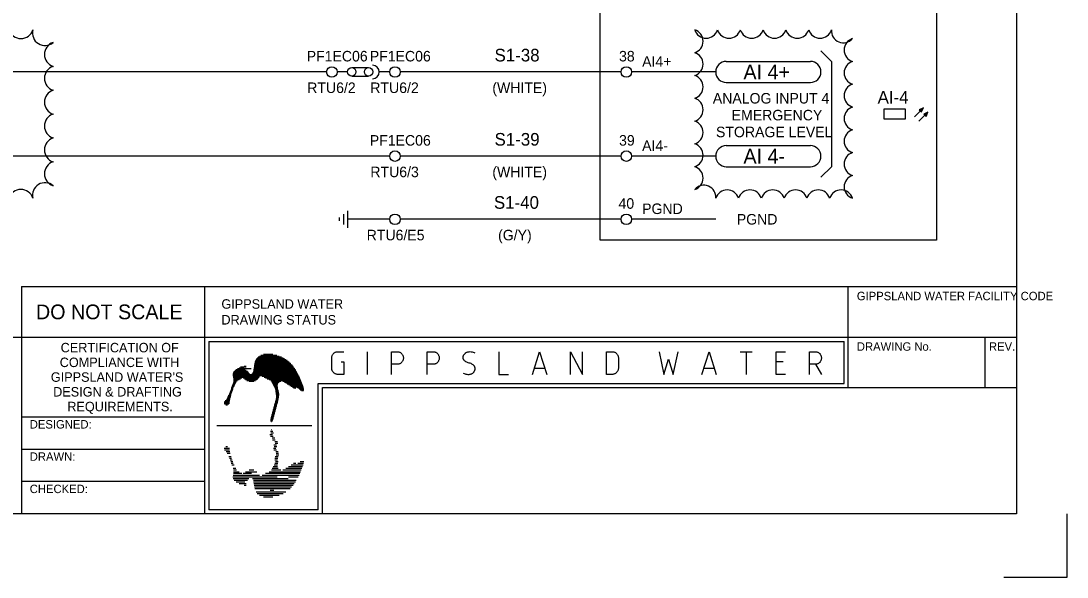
# Model space of a CAD drawing. Extents: x 0 to 841, y 0 to 594.
# Drawn here: x 592.3 to 841, y 0 to 132.1 of the extents above; entities that cross this region are included whole.
import ezdxf

# ---------------------------------------------------------------- set-up
doc = ezdxf.new("R2010")
doc.units = 0
for name, color, linetype in [('A1BORDER', 7, 'Continuous'), ('Level 1', 7, 'Continuous'), ('Level 10', 7, 'Continuous')]:
    doc.layers.add(name, color=color, linetype=linetype)

msp = doc.modelspace()

# ---------------------------------------------------------------- linework, layer by layer
at = {"layer": 'A1BORDER'}
for p, q in [((829, 581), (829, 15)), ((592.5, 69), (592.5, 15)), ((592.5, 69), (829, 69)), ((636, 69), (636, 15)), ((789, 45), (789, 69)), ((28, 57), (829, 57)), ((637, 56), (788, 56)), ((637, 56), (637, 16)), ((788, 46), (788, 56)), ((821.5, 45), (821.5, 57)), ((648.74, 52.32), (654.24, 52.32)), ((649.02, 52.52), (653.76, 52.52)), ((649.39, 52.72), (653.15, 52.72)), ((650.01, 52.92), (652.2, 52.92)), ((644.54, 49.92), (645.36, 49.92)), ((645.37, 50.12), (645.86, 50.12)), ((647.75, 49.92), (657.17, 49.92)), ((647.78, 50.12), (657.02, 50.12)), ((647.81, 50.32), (656.86, 50.32)), ((647.85, 50.52), (656.69, 50.52)), ((647.88, 50.72), (656.5, 50.72)), ((647.91, 50.92), (656.3, 50.92)), ((647.96, 51.12), (656.08, 51.12)), ((648.03, 51.32), (655.85, 51.32)), ((648.12, 51.52), (655.59, 51.52)), ((648.23, 51.72), (655.31, 51.72)), ((648.37, 51.92), (655, 51.92)), ((648.53, 52.12), (654.64, 52.12)), ((642.73, 48.12), (658.25, 48.12)), ((642.74, 47.92), (658.35, 47.92)), ((642.75, 48.32), (646.79, 48.32)), ((642.79, 47.72), (649.08, 47.72)), ((642.81, 48.52), (646.55, 48.52)), ((642.83, 47.52), (648.95, 47.52)), ((642.85, 47.31), (644.88, 47.31)), ((642.9, 48.72), (646.37, 48.72)), ((643.04, 48.92), (646.16, 48.92)), ((643.26, 49.12), (645.9, 49.12)), ((643.54, 49.32), (645.57, 49.32)), ((643.85, 49.52), (647.09, 49.52)), ((644.18, 49.72), (645.89, 49.72)), ((645.14, 47.31), (648.83, 47.31)), ((647.19, 48.32), (658.14, 48.32)), ((647.42, 48.52), (658.03, 48.52)), ((647.54, 48.72), (657.92, 48.72)), ((647.61, 48.92), (657.8, 48.92)), ((647.63, 49.12), (657.68, 49.12)), ((647.66, 49.32), (657.57, 49.32)), ((647.69, 49.52), (657.44, 49.52)), ((647.71, 49.72), (657.31, 49.72)), ((649.72, 47.72), (658.45, 47.72)), ((650.12, 47.52), (658.55, 47.52)), ((650.48, 47.31), (658.64, 47.31)), ((642.35, 44.92), (642.83, 44.92)), ((642.43, 45.12), (642.9, 45.12)), ((642.5, 45.32), (643, 45.32)), ((642.57, 45.52), (643.1, 45.52)), ((642.65, 45.72), (643.2, 45.72)), ((642.72, 45.92), (643.3, 45.92)), ((642.79, 46.12), (643.4, 46.12)), ((642.84, 46.32), (643.5, 46.32)), ((642.87, 47.12), (644.57, 47.12)), ((642.87, 46.52), (643.6, 46.52)), ((642.88, 46.92), (644.23, 46.92)), ((642.88, 46.72), (643.83, 46.72)), ((645.49, 47.12), (648.67, 47.12)), ((645.76, 46.92), (648.42, 46.92)), ((646.05, 46.72), (648.11, 46.72)), ((646.62, 46.52), (647.67, 46.52)), ((650.87, 47.12), (658.73, 47.12)), ((651.36, 46.92), (658.82, 46.92)), ((651.76, 46.72), (658.9, 46.72)), ((651.88, 46.52), (654.15, 46.52)), ((651.99, 46.32), (653.71, 46.32)), ((652.1, 46.12), (653.52, 46.12)), ((652.2, 45.92), (653.4, 45.92)), ((652.31, 45.72), (653.33, 45.72)), ((652.41, 45.52), (653.31, 45.52)), ((652.5, 45.32), (653.34, 45.32)), ((652.6, 45.12), (653.38, 45.12)), ((652.69, 44.92), (653.41, 44.92)), ((654.57, 46.52), (658.99, 46.52)), ((655, 46.32), (659.07, 46.32)), ((655.31, 46.12), (659.14, 46.12)), ((655.62, 45.92), (659.22, 45.92)), ((655.93, 45.72), (659.29, 45.72)), ((656.24, 45.52), (659.35, 45.52)), ((656.55, 45.32), (659.42, 45.32)), ((656.86, 45.12), (657.74, 45.12)), ((657.17, 44.92), (657.68, 44.92)), ((657.91, 45.12), (659.48, 45.12)), ((658.19, 44.92), (659.54, 44.92)), ((663, 46), (788, 46)), ((663, 16), (663, 46)), ((664, 45), (829, 45)), ((664, 15), (664, 45)), ((641.25, 42.31), (642.04, 42.31)), ((641.37, 42.52), (642.09, 42.52)), ((641.46, 42.72), (642.15, 42.72)), ((641.55, 42.92), (642.2, 42.92)), ((641.64, 43.12), (642.25, 43.12)), ((641.73, 43.32), (642.3, 43.32)), ((641.82, 43.51), (642.35, 43.51)), ((641.91, 43.72), (642.41, 43.72)), ((641.99, 43.92), (642.48, 43.92)), ((642.06, 44.12), (642.55, 44.12)), ((642.13, 44.32), (642.62, 44.32)), ((642.21, 44.52), (642.69, 44.52)), ((642.28, 44.72), (642.76, 44.72)), ((652.78, 44.72), (653.44, 44.72)), ((652.83, 44.52), (653.48, 44.52)), ((652.86, 44.32), (653.53, 44.32)), ((652.89, 44.12), (653.57, 44.12)), ((652.91, 43.92), (653.62, 43.92)), ((652.94, 43.72), (653.67, 43.72)), ((652.95, 42.31), (653.53, 42.31)), ((652.97, 43.51), (653.71, 43.51)), ((652.99, 42.52), (653.57, 42.52)), ((653, 43.32), (653.69, 43.32)), ((653.02, 43.12), (653.67, 43.12)), ((653.03, 42.72), (653.61, 42.72)), ((653.05, 42.92), (653.64, 42.92)), ((657.51, 44.72), (657.54, 44.72)), ((658.47, 44.72), (659.59, 44.72)), ((658.75, 44.52), (659.58, 44.52)), ((659.02, 44.32), (659.47, 44.32)), ((640.62, 41.32), (641.88, 41.32)), ((640.63, 41.52), (641.93, 41.52)), ((640.72, 41.12), (641.73, 41.12)), ((640.73, 41.72), (641.95, 41.72)), ((640.9, 41.92), (641.97, 41.92)), ((641.03, 40.92), (641.43, 40.92)), ((641.1, 42.12), (642, 42.12)), ((652.3, 39.92), (652.93, 39.92)), ((652.36, 40.12), (652.99, 40.12)), ((652.41, 40.32), (653.04, 40.32)), ((652.47, 40.52), (653.1, 40.52)), ((652.52, 40.72), (653.15, 40.72)), ((652.57, 40.92), (653.2, 40.92)), ((652.63, 41.12), (653.26, 41.12)), ((652.68, 41.32), (653.31, 41.32)), ((652.74, 41.52), (653.37, 41.52)), ((652.79, 41.72), (653.41, 41.72)), ((652.85, 41.92), (653.45, 41.92)), ((652.9, 42.12), (653.49, 42.12)), ((636, 38), (592.5, 38)), ((651.63, 37.32), (652.23, 37.32)), ((651.65, 37.52), (652.28, 37.52)), ((651.71, 37.72), (652.34, 37.72)), ((651.76, 37.92), (652.39, 37.92)), ((651.82, 38.12), (652.44, 38.12)), ((651.87, 38.32), (652.5, 38.32)), ((651.92, 38.52), (652.55, 38.52)), ((651.98, 38.72), (652.61, 38.72)), ((652.03, 38.92), (652.66, 38.92)), ((652.09, 39.12), (652.72, 39.12)), ((652.14, 39.32), (652.77, 39.32)), ((652.2, 39.52), (652.82, 39.52)), ((652.25, 39.72), (652.88, 39.72)), ((638.93, 35.98), (661.47, 35.98)), ((651.64, 37.12), (652.17, 37.12)), ((651.79, 36.92), (651.9, 36.92)), ((651.79, 35.04), (651.9, 35.04)), ((651.54, 33.84), (652.17, 33.84)), ((651.63, 34.64), (652.23, 34.64)), ((651.65, 33.44), (652.28, 33.44)), ((651.71, 34.24), (652.34, 34.24)), ((652.03, 33.04), (652.66, 33.04)), ((652.14, 32.64), (652.77, 32.64)), ((636, 30.34), (592.5, 30.34)), ((640.62, 30.64), (641.88, 30.64)), ((640.73, 30.24), (641.95, 30.24)), ((641.03, 31.04), (641.43, 31.04)), ((641.1, 29.84), (642, 29.84)), ((652.34, 30.64), (652.97, 30.64)), ((652.45, 30.24), (653.07, 30.24)), ((652.47, 31.44), (653.1, 31.44)), ((652.57, 31.04), (653.2, 31.04)), ((652.66, 32.24), (653.29, 32.24)), ((652.77, 31.84), (653.4, 31.84)), ((652.9, 29.84), (653.49, 29.84)), ((641.37, 29.44), (642.09, 29.44)), ((641.73, 28.64), (642.3, 28.64)), ((641.91, 28.24), (642.41, 28.24)), ((642.06, 27.84), (642.55, 27.84)), ((642.21, 27.44), (642.69, 27.44)), ((652.66, 27.84), (653.35, 27.84)), ((652.72, 28.24), (653.44, 28.24)), ((652.77, 28.64), (653.46, 28.64)), ((652.83, 27.44), (653.48, 27.44)), ((652.99, 29.44), (653.57, 29.44)), ((653.05, 29.04), (653.64, 29.04)), ((658.75, 27.44), (659.58, 27.44)), ((642.35, 27.04), (642.83, 27.04)), ((642.5, 26.64), (643, 26.64)), ((642.79, 25.84), (643.4, 25.84)), ((642.87, 25.44), (643.6, 25.44)), ((642.88, 25.04), (644.23, 25.04)), ((645.76, 25.04), (648.42, 25.04)), ((646.62, 25.44), (647.67, 25.44)), ((651.36, 25.04), (658.82, 25.04)), ((651.88, 25.44), (654.15, 25.44)), ((652.1, 25.84), (653.52, 25.84)), ((652.31, 26.24), (653.33, 26.24)), ((652.5, 26.64), (653.34, 26.64)), ((652.69, 27.04), (653.41, 27.04)), ((654.57, 25.44), (658.99, 25.44)), ((655.31, 25.84), (659.14, 25.84)), ((655.93, 26.24), (659.29, 26.24)), ((656.55, 26.64), (659.42, 26.64)), ((657.17, 27.04), (657.68, 27.04)), ((658.19, 27.04), (659.54, 27.04)), ((636, 22.67), (592.5, 22.67)), ((642.73, 23.84), (653.27, 23.84)), ((642.79, 24.24), (649.08, 24.24)), ((642.81, 23.44), (646.55, 23.44)), ((642.85, 24.65), (644.88, 24.65)), ((643.04, 23.04), (646.16, 23.04)), ((643.54, 22.64), (645.57, 22.64)), ((645.14, 24.65), (647.18, 24.65)), ((647.42, 23.44), (655.89, 23.44)), ((647.61, 23.04), (657.8, 23.04)), ((647.66, 22.64), (657.57, 22.64)), ((649.72, 24.24), (658.45, 24.24)), ((650.48, 24.65), (658.64, 24.65)), ((655.94, 23.84), (658.25, 23.84)), ((644.18, 22.24), (645.89, 22.24)), ((645.37, 21.84), (645.86, 21.84)), ((647.71, 22.24), (657.31, 22.24)), ((647.78, 21.84), (657.02, 21.84)), ((647.85, 21.44), (656.69, 21.44)), ((647.91, 21.04), (656.3, 21.04)), ((648.23, 20.24), (655.31, 20.24)), ((651.57, 20.64), (652.44, 20.64)), ((648.53, 19.84), (654.64, 19.84)), ((649.02, 19.44), (653.76, 19.44)), ((650.01, 19.04), (652.2, 19.04)), ((829, 15), (28, 15)), ((663, 16), (637, 16)), ((829, 15), (829, 15)), ((841, 0), (841, 15)), ((826, 0), (841, 0))]:
    msp.add_line(p, q, dxfattribs=at)
for points in [[(668.49, 51.15), (669.06, 51.15), (669.06, 48.16), (667.64, 48.16), (667.51, 48.16), (667.39, 48.18), (667.28, 48.21), (667.15, 48.25), (667.04, 48.3), (666.93, 48.36), (666.82, 48.43), (666.73, 48.51), (666.64, 48.6), (666.55, 48.7), (666.48, 48.8), (666.41, 48.91), (666.35, 49.02), (666.31, 49.14), (666.27, 49.27), (666.24, 49.39), (666.22, 49.52), (666.22, 49.66), (666.22, 52.05), (666.22, 52.18), (666.24, 52.31), (666.27, 52.43), (666.31, 52.56), (666.35, 52.67), (666.41, 52.79), (666.48, 52.9), (666.55, 53), (666.64, 53.1), (666.73, 53.19), (666.82, 53.27), (666.93, 53.34), (667.04, 53.4), (667.15, 53.45), (667.28, 53.49), (667.39, 53.52), (667.51, 53.54), (667.64, 53.54), (669.06, 53.54)], [(674.74, 48.16), (674.74, 53.54)], [(680.42, 48.16), (680.42, 53.54), (681.84, 53.54), (681.96, 53.54), (682.08, 53.52), (682.2, 53.49), (682.32, 53.45), (682.43, 53.4), (682.54, 53.34), (682.65, 53.27), (682.74, 53.19), (682.84, 53.1), (682.92, 53), (682.99, 52.9), (683.06, 52.79), (683.12, 52.67), (683.17, 52.56), (683.21, 52.43), (683.23, 52.31), (683.25, 52.18), (683.26, 52.05), (683.25, 51.91), (683.23, 51.78), (683.21, 51.66), (683.17, 51.53), (683.12, 51.42), (683.06, 51.3), (682.99, 51.19), (682.92, 51.09), (682.84, 50.99), (682.74, 50.9), (682.65, 50.82), (682.54, 50.75), (682.43, 50.69), (682.32, 50.64), (682.2, 50.6), (682.08, 50.57), (681.96, 50.55), (681.84, 50.55), (680.42, 50.55)], [(688.93, 48.16), (688.93, 53.54), (690.35, 53.54), (690.47, 53.54), (690.59, 53.52), (690.71, 53.49), (690.83, 53.45), (690.94, 53.4), (691.05, 53.34), (691.16, 53.27), (691.26, 53.19), (691.35, 53.1), (691.43, 53), (691.51, 52.9), (691.57, 52.79), (691.63, 52.67), (691.68, 52.56), (691.72, 52.43), (691.75, 52.31), (691.76, 52.18), (691.77, 52.05), (691.76, 51.91), (691.75, 51.78), (691.72, 51.66), (691.68, 51.53), (691.63, 51.42), (691.57, 51.3), (691.51, 51.19), (691.43, 51.09), (691.35, 50.99), (691.26, 50.9), (691.16, 50.82), (691.05, 50.75), (690.94, 50.69), (690.83, 50.64), (690.71, 50.6), (690.59, 50.57), (690.47, 50.55), (690.35, 50.55), (688.93, 50.55)], [(697.45, 48.46), (697.67, 48.36), (697.9, 48.27), (698.12, 48.21), (698.36, 48.17), (698.6, 48.16), (698.84, 48.16), (698.87, 48.16), (699.03, 48.18), (699.18, 48.21), (699.33, 48.26), (699.48, 48.32), (699.62, 48.4), (699.72, 48.46), (699.81, 48.53), (699.9, 48.61), (699.98, 48.69), (700.05, 48.78), (700.11, 48.88), (700.17, 48.99), (700.22, 49.09), (700.25, 49.21), (700.28, 49.32), (700.29, 49.36), (700.3, 49.44), (700.3, 49.52), (700.3, 49.61), (700.29, 49.69), (700.27, 49.77), (700.25, 49.86), (700.22, 49.93), (700.18, 50.01), (700.14, 50.09), (700.09, 50.15), (700.04, 50.21), (700.01, 50.25), (699.85, 50.39), (699.69, 50.51), (699.52, 50.61), (699.34, 50.7), (699.15, 50.78), (698.95, 50.83), (698.87, 50.85), (698.68, 50.9), (698.49, 50.96), (698.3, 51.04), (698.12, 51.14), (697.96, 51.26), (697.8, 51.39), (697.73, 51.45), (697.67, 51.51), (697.62, 51.57), (697.58, 51.64), (697.53, 51.71), (697.5, 51.79), (697.47, 51.87), (697.46, 51.95), (697.44, 52.04), (697.43, 52.12), (697.43, 52.21), (697.44, 52.29), (697.45, 52.35), (697.47, 52.46), (697.51, 52.58), (697.55, 52.69), (697.61, 52.79), (697.67, 52.89), (697.74, 52.99), (697.82, 53.07), (697.9, 53.15), (697.99, 53.23), (698.02, 53.24), (698.15, 53.33), (698.3, 53.4), (698.44, 53.45), (698.6, 53.5), (698.75, 53.52), (698.87, 53.54), (699.11, 53.55), (699.35, 53.53), (699.58, 53.49), (699.82, 53.43), (700.04, 53.35), (700.27, 53.25)], [(705.96, 53.54), (705.96, 48.16), (708.23, 48.16)], [(713.91, 48.16), (715.61, 53.54), (717.32, 48.16)], [(722.99, 48.16), (722.99, 53.54), (725.83, 48.16), (725.83, 53.54)], [(731.52, 48.16), (731.52, 53.54), (732.94, 53.54), (733.06, 53.54), (733.18, 53.52), (733.3, 53.49), (733.42, 53.45), (733.53, 53.4), (733.64, 53.34), (733.75, 53.27), (733.84, 53.19), (733.94, 53.1), (734.02, 53), (734.09, 52.9), (734.16, 52.79), (734.22, 52.67), (734.27, 52.56), (734.31, 52.43), (734.33, 52.31), (734.35, 52.18), (734.36, 52.05), (734.36, 49.66), (734.35, 49.52), (734.33, 49.39), (734.31, 49.27), (734.27, 49.14), (734.22, 49.02), (734.16, 48.91), (734.09, 48.8), (734.02, 48.7), (733.94, 48.6), (733.84, 48.51), (733.75, 48.43), (733.64, 48.36), (733.53, 48.3), (733.42, 48.25), (733.3, 48.21), (733.18, 48.18), (733.06, 48.16), (732.94, 48.16), (731.52, 48.16)], [(744.01, 53.54), (745.14, 48.16), (746.28, 51.75), (747.41, 48.16), (748.55, 53.54)], [(754.22, 48.16), (755.92, 53.54), (757.63, 48.16)], [(763.31, 53.54), (766.15, 53.54)], [(764.73, 53.54), (764.73, 48.16)], [(774.09, 48.16), (771.82, 48.16), (771.82, 53.54), (774.09, 53.54)], [(779.78, 48.16), (779.78, 53.54), (781.2, 53.54), (781.32, 53.54), (781.44, 53.52), (781.56, 53.49), (781.68, 53.45), (781.79, 53.4), (781.9, 53.34), (782.01, 53.27), (782.1, 53.19), (782.2, 53.1), (782.28, 53), (782.35, 52.9), (782.42, 52.79), (782.48, 52.67), (782.53, 52.56), (782.56, 52.43), (782.59, 52.31), (782.61, 52.18), (782.61, 52.05), (782.61, 51.91), (782.59, 51.78), (782.56, 51.66), (782.53, 51.53), (782.48, 51.42), (782.42, 51.3), (782.35, 51.19), (782.28, 51.09), (782.2, 50.99), (782.1, 50.9), (782.01, 50.82), (781.9, 50.75), (781.79, 50.69), (781.68, 50.64), (781.56, 50.6), (781.44, 50.57), (781.32, 50.55), (781.2, 50.55), (779.78, 50.55)], [(773.53, 51.15), (771.82, 51.15)], [(781.2, 50.55), (782.61, 48.16)], [(714.48, 49.66), (716.75, 49.66)], [(754.79, 49.66), (757.06, 49.66)]]:
    msp.add_lwpolyline(points, dxfattribs=at)
at = {"layer": 'Level 1'}
for p, q in [((760, 122.5), (780, 122.5)), ((665, 120), (480, 120)), ((670, 120), (667.5, 120)), ((670.98, 121.03), (674.98, 121.03)), ((680, 120), (677.5, 120)), ((735, 120), (682.5, 120)), ((757.5, 120), (737.5, 120)), ((670.98, 119.03), (674.98, 119.03)), ((760, 117.5), (780, 117.5)), ((760, 102.5), (780, 102.5)), ((680, 100), (480, 100)), ((735, 100), (682.5, 100)), ((757.5, 100), (737.5, 100)), ((760, 97.5), (780, 97.5)), ((680, 85), (670, 85)), ((735, 85), (682.5, 85)), ((757.5, 85), (737.5, 85))]:
    msp.add_line(p, q, dxfattribs=at)
for points in [[(810, 553.95), (810, 80), (730, 80), (730, 546.05)], [(782.5, 125), (785, 122.5), (785, 97.5), (782.5, 95)]]:
    msp.add_lwpolyline(points, dxfattribs=at)
msp.add_lwpolyline([(797.5, 111.25), (802.5, 111.25), (802.5, 108.75), (797.5, 108.75)], close=True, dxfattribs=at)
for centre in [(670.98, 120.03), (674.98, 120.03)]:
    msp.add_circle(centre, 1, dxfattribs=at)
for centre, radius, start, end in [((592.35, 130.89), 2.97, 197.5, 342.5), ((598.06, 129.26), 2.98, 165.5651, 310.5651), ((755.21, 130.85), 2.84, 197.5, 342.5), ((751.65, 127.29), 2.84, 287.5, 72.5), ((760.63, 130.85), 2.84, 197.5, 342.5), ((766.04, 130.85), 2.84, 197.5, 342.5), ((771.46, 130.85), 2.84, 197.5, 342.5), ((776.88, 130.85), 2.84, 197.5, 342.5), ((782.29, 130.85), 2.84, 197.5, 342.5), ((787.83, 129.75), 2.84, 174.9059, 319.9059), ((600.89, 124.16), 2.97, 107.5, 252.5), ((790.85, 125.21), 2.84, 107.5, 252.5), ((751.65, 121.87), 2.84, 287.5, 72.5), ((760, 120), 2.5, 90, 270), ((780, 120), 2.5, 270, 90), ((790.85, 119.79), 2.84, 107.5, 252.5), ((600.89, 118.49), 2.97, 107.5, 252.5), ((751.65, 116.46), 2.84, 287.5, 72.5), ((790.85, 114.38), 2.84, 107.5, 252.5), ((600.89, 112.82), 2.97, 107.5, 252.5), ((751.65, 111.04), 2.84, 287.5, 72.5), ((600.89, 107.15), 2.97, 107.5, 252.5), ((790.85, 108.96), 2.84, 107.5, 252.5), ((751.65, 105.62), 2.84, 287.5, 72.5), ((790.85, 103.54), 2.84, 107.5, 252.5), ((600.89, 101.48), 2.97, 107.5, 252.5), ((751.65, 100.21), 2.84, 287.5, 72.5), ((760, 100), 2.5, 90, 270), ((780, 100), 2.5, 270, 90), ((790.85, 98.13), 2.84, 107.5, 252.5), ((600.89, 95.81), 2.97, 107.5, 252.5), ((751.65, 94.79), 2.84, 287.5, 72.5), ((790.85, 92.71), 2.84, 107.5, 252.5), ((592.34, 89.11), 2.97, 17.5, 162.5), ((598.06, 90.73), 2.97, 49.1699, 194.1699), ((754.67, 90.25), 2.84, 354.9059, 139.9059), ((760.21, 89.15), 2.84, 17.5, 162.5), ((765.62, 89.15), 2.84, 17.5, 162.5), ((771.04, 89.15), 2.84, 17.5, 162.5), ((776.46, 89.15), 2.84, 17.5, 162.5), ((781.87, 89.15), 2.84, 17.5, 162.5), ((787.29, 89.15), 2.84, 17.5, 162.5)]:
    msp.add_arc(centre, radius, start, end, dxfattribs=at)
at = {"layer": 'Level 10'}
for p, q in [((804.73, 109.36), (806.86, 111.48)), ((805.79, 108.3), (807.91, 110.42)), ((805.96, 111.08), (806.67, 111.08)), ((806, 110.92), (806.61, 110.92)), ((806.14, 110.78), (806.53, 110.78)), ((806.29, 111.23), (806.74, 111.23)), ((806.3, 110.62), (806.47, 110.62)), ((806.62, 111.38), (806.81, 111.38)), ((807.02, 110.02), (807.73, 110.02)), ((807.06, 109.87), (807.66, 109.87)), ((807.21, 109.72), (807.6, 109.72)), ((807.35, 110.17), (807.8, 110.17)), ((807.36, 109.56), (807.53, 109.56)), ((807.68, 110.31), (807.87, 110.31)), ((668, 85.4), (668, 84.6)), ((669, 86.2), (669, 83.8)), ((670, 87), (670, 83))]:
    msp.add_line(p, q, dxfattribs=at)
for points in [[(806.86, 111.48), (805.88, 111.04), (806.41, 110.5)], [(807.91, 110.42), (806.94, 109.98), (807.48, 109.45)]]:
    msp.add_lwpolyline(points, close=True, dxfattribs=at)
for centre in [(666.25, 120), (681.25, 120), (736.25, 120), (681.25, 100), (736.25, 100), (681.25, 85), (736.25, 85)]:
    msp.add_circle(centre, 1.25, dxfattribs=at)
msp.add_arc((675.9, 120), 1.6, 270, 90, dxfattribs=at)

# ---------------------------------------------------------------- texts
at = {"layer": 'A1BORDER'}
for s, height, p in [('GIPPSLAND WATER FACILITY CODE', 2, (791.03, 65.77)), ('DO NOT SCALE', 3.5, (595.92, 61.25)), ('GIPPSLAND WATER', 2.25, (640, 63.75)), ('DRAWING STATUS', 2.25, (640, 60)), ('CERTIFICATION OF', 2.25, (601.79, 53.39)), ('DRAWING No.', 2, (791.03, 53.77)), ('REV.', 2, (822.43, 53.77)), ('COMPLIANCE WITH', 2.25, (601.57, 49.89)), ("GIPPSLAND WATER'S", 2.25, (599.45, 46.39)), ('DESIGN & DRAFTING', 2.25, (600, 42.89)), ('REQUIREMENTS.', 2.25, (603.37, 39.39)), ('DESIGNED:', 2, (594.44, 35.29)), ('DRAWN:', 2, (594.44, 27.62)), ('CHECKED:', 2, (594.44, 19.95))]:
    msp.add_text(s, height=height, dxfattribs=at).set_placement(p)
at = {"layer": 'Level 1'}
for s, height, p in [('PF1EC06', 2.5, (660.27, 122.5)), ('PF1EC06', 2.5, (675.27, 122.5)), ('S1-38', 3, (704.92, 122.5)), ('38', 2.5, (734.51, 122.5)), ('AI4+', 2.5, (740, 121.25)), ('AI 4+', 3.5, (764.08, 118.25)), ('RTU6/2', 2.5, (660.39, 115)), ('RTU6/2', 2.5, (675.39, 115)), ('(WHITE)', 2.5, (704.39, 115)), ('ANALOG INPUT 4', 2.5, (756.8, 112.5)), ('AI-4', 3, (795.97, 112.5)), ('EMERGENCY', 2.5, (761.28, 108.5)), ('STORAGE LEVEL', 2.5, (757.55, 104.5)), ('PF1EC06', 2.5, (675.27, 102.5)), ('S1-39', 3, (704.92, 102.5)), ('39', 2.5, (734.51, 102.5)), ('AI4-', 2.5, (740, 101.25)), ('AI 4-', 3.5, (764.08, 98.25)), ('RTU6/3', 2.5, (675.4, 95)), ('(WHITE)', 2.5, (704.39, 95)), ('S1-40', 3, (704.77, 87.5)), ('40', 2.5, (734.38, 87.5)), ('PGND', 2.5, (740, 86.25)), ('PGND', 2.5, (762.5, 83.75)), ('RTU6/E5', 2.5, (674.53, 80)), ('(G/Y)', 2.5, (705.76, 80))]:
    msp.add_text(s, height=height, dxfattribs=at).set_placement(p)

doc.saveas('drawing.dxf')
